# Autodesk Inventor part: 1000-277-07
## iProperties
Created: 2007-03
Part Number: 1000-277-07
Document SubType Name: Modeling
Designer: Andy Moles
Material: Steel
Mass: 10.9183 g
Surface Area: 12.2476 cm^2
Volume: 1.39086 cm^3
Density: 7.85 g/cm^3
Author: Andy Moles
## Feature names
1. Base1
